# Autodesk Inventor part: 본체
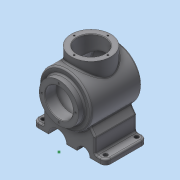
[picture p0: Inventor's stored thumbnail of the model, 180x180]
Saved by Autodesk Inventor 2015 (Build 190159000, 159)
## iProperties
Created: 2018-08
Part Number: 본체
Material: 알루미늄 6061
Document SubType Name: Modeling
Designer: SCD-A18
Density: 2.7 g/cm^3
Appearance: 기본값
Mass: 1879.08 g
Surface Area: 1087.45 cm^2
Volume: 695.956 cm^3
Author: SCD-A18
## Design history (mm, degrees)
sketch "스케치2"
  geometry: L1 (0, 0)-(120, 0); L2 (0, 0)-(0, 27); L3 (0, 38)-(12, 38); L4 (12, 38)-(12, 50); L5 (12, 50)-(120, 50); L6 (120, 50)-(120, 0); L7 (0, 27)-(22, 27); L8 (22, 27)-(22, 40); L9 (22, 40)-(133.746, 40); L10 (0, 0)-(0, 27); L11 (0, 27)-(0, 38); A1 r 116 centre (4, 0) between (120, 0) and (108.671, 50); A2 r 106 centre (4, 0) between (107.419, -23.249) and (102.163, 40)
  constraints: 22 end point, 5 perpendicular, 4 horizontal, 4 point on circle, 3 point on line, 2 centre point, 2 collinear, 2 vertical, 1 coincident
  dimensions: "d0" = 120 distance of L1.end L1.start; "d1" = 76 diameter of L3 L1; "d5" = 12 distance of L3.start L3.end; "d6" = 116 radius of A1; "d9" = 100 diameter of L5 L1; "d10" = 54 diameter of L7 L1; "d12" = 22 distance of L2.end L7.end; "d15" = 106 radius of A2; "d16" = 80 diameter of L9 L1
revolve "회전1" sketch "스케치2" stored, may be unused: angle "d17" = 90 deg
node "작업 평면1"
sketch "스케치3"
  geometry: L1 (0, -38)-(0, 38) reference; L2 (0, 0)-(0, 27); L3 (0, 27)-(22, 27); L4 (22, 27)-(22, 40); L5 (22, 40)-(102.163, 40); L6 (0, 0)-(110, 0); A1 r 116 centre (4, 0) between (108.671, -50) and (108.671, 50) reference; A2 r 106 centre (4, 0) between (110, 0) and (102.163, 40)
  constraints: 10 end point, 3 perpendicular, 2 point on circle, 1 centre point, 1 coincident, 1 horizontal, 1 point on line
  dimensions: "d19" = 10 radial gap between concentric circles of A1 A2; "d20" = 22 distance of L2.end L3.end; "d21" = 54 diameter of L3 L6; "d22" = 80 diameter of L5 L6
revolve "회전2" sketch "스케치3" stored, may be unused: angle "d23" = 90 deg
fillet "모깎기1" dims "d24" = 3
chamfer "모따기1" distance "d25" = 1; stored, may be unused: second distance "d26" = 2, angle "d27" = 45 deg
node "작업 평면2"
node "작업 평면3"
sketch "스케치5"
  geometry: 1 further point
sketch "스케치6"
  geometry: L1 (-20, -70)-(-100, -70); L2 (-100, -70)-(-100, 70); L3 (-100, 70)-(-20, 70); L4 (-20, 70)-(-20, -70); L5 (0, 38)-(0, -38) reference; L6 (-108.671, 50)-(-108.671, -50) reference; L7 (0, 0)-(-120, 0); A1 r 116 centre (-4, 0) between (-108.671, 50) and (-108.671, -50) reference; 3 further points
  constraints: 10 end point, 3 midpoint, 2 parallel, 1 horizontal, 1 horizontal alignment, 1 perpendicular, 1 point on circle, 1 vertical alignment
  dimensions: "d41" = 80 distance of L1.start L1.end; "d42" = 140 distance of L3.end L1.start
extrude "돌출1" join sketch "스케치6" distance "d43" = 10; taper "d44" = 0 deg
sketch "스케치7"
  geometry: L1 (100, 70)-(20, 70) reference; L2 (20, 70)-(20, -70) reference; L3 (20, 50)-(100, 50); L4 (100, 50)-(100, -50); L5 (100, -50)-(20, -50); L6 (20, -50)-(20, 50); 5 further points
  constraints: 8 end point, 4 midpoint, 2 parallel, 1 coincident, 1 collinear, 1 horizontal, 1 perpendicular, 1 vertical alignment
  dimensions: "d45" = 20 distance between parallel lines of L3 L1
extrude "돌출2" join sketch "스케치7" stored distance "d46" = 10; taper "d47" = 0 deg
sketch "스케치8"
  geometry: L1 (140, 0)-(140, 10) reference; L2 (120, 10)-(120, 82) reference; L3 (20, 10)-(20, 82) reference; L4 (0, 0)-(0, 10) reference; L5 (0, 10)-(29.696, 52.41); L6 (140, 10)-(110.304, 52.41); L7 (20, 38.563)-(20, 82); L8 (120, 38.563)-(120, 82); C1 r 50 at (70, 82); A1 r 50 centre (70, 82) between (20, 82) and (120, 82) reference; A2 r 50 centre (70, 82) between (120, 82) and (20, 82) reference
  constraints: 8 end point, 4 point on line, 2 collinear, 2 point on circle, 2 tangent, 1 centre point, 1 coincident, 1 concentric
  dimensions: "d49" = 35 deg angle of L5 L4; "d51" = 35 deg angle of L6 L1
extrude "돌출3" cut sketch "스케치8" stored distance "d52" = 10; taper "d53" = 0 deg
fillet "모깎기2" dims "d54" = 10
fillet "모깎기3" dims "d55" = 3
node "작업 평면4"
sketch "스케치9"
  geometry: L1 (12, -47)-(12, 47) reference; L2 (12, 0)-(120, 0); L3 (0, -38)-(0, 38) reference; C1 r 38 at (62, 0); A1 r 116 centre (4, 0) between (109.49, -48.248) and (109.49, 48.248) reference; 1 further point
  constraints: 2 end point, 1 centre point, 1 midpoint, 1 point on circle, 1 point on line
  dimensions: "d63" = 76 diameter of C1; "d64" = 62 distance from line of L3 C1.centre
extrude "돌출4" join sketch "스케치9" stored distance "d61" = 10; taper "d62" = 0 deg
fillet "모깎기7" dims "d65" = 3
sketch "스케치11"
  geometry: C1 r 38 at (0, 0) reference; C2 r 27 at (0, 0); 1 further point
  constraints: 1 centre point, 1 coincident
  dimensions: "d66" = 54 diameter of C2
extrude "돌출5" cut sketch "스케치11" stored distance "d67" = 10; taper "d68" = 0 deg
sketch "스케치12"
  geometry: C1 r 27 at (0, 0) reference; 5 further points
  constraints: 1 vertical alignment, 5 other
  dimensions: "d69" = 32.5 distance of C1.centre point (0, 32.5); "d72" = 360 deg dimension on C1.centre point (0, 32.5) (derived)
hole "구멍1" sketch "스케치12" at (0, 32.5), (32.5, 0), (0, -32.5), (-32.5, 0) diameter "d74" = 3.242; stored, may be unused: countersink angle "d78" = 90 deg, drill point angle "d80" = 118 deg; dims "d75" = 8, "d76" = 4, "d77" = 2, "d79" = 10
sketch "스케치13"
  geometry: C1 r 38 at (0, 0) reference; 4 further points
  constraints: 1 horizontal alignment, 5 other
  dimensions: "d81" = 32.5 distance of C1.centre point (32.5, 0); "d84" = 360 deg dimension on C1.centre point (32.5, 0) (derived)
hole "구멍2" sketch "스케치13" at (0, 32.5), (-32.5, 0), (0, -32.5), (32.5, 0) diameter "d86" = 3.242; stored, may be unused: countersink angle "d90" = 90 deg, drill point angle "d92" = 118 deg; dims "d87" = 8, "d88" = 4, "d89" = 2, "d91" = 10
chamfer "모따기2" distance "d93" = 1; stored, may be unused: second distance "d94" = 2, angle "d95" = 45 deg
node "작업 평면5"
sketch "스케치15"
  geometry: A1 r 10 centre (90, 60) between (100, 60) and (90, 70) reference; A2 r 10 centre (30, 60) between (30, 70) and (20, 60) reference; A3 r 10 centre (30, -60) between (20, -60) and (30, -70) reference; A4 r 10 centre (90, -60) between (90, -70) and (100, -60) reference; 5 further points
  constraints: 4 coincident
hole "구멍3" sketch "스케치15" at (90, -60), (30, -60), (30, 60), (90, 60) diameter "d98" = 8; stored, may be unused: countersink angle "d102" = 90 deg, drill point angle "d104" = 0 deg; dims "d99" = 8, "d100" = 4, "d101" = 2, "d103" = 10
node "작업 평면6"
sketch "스케치16"
  geometry: C1 r 32.5 at (0, 0); 1 further point
  constraints: 1 centre point, 1 coincident, 1 other
  dimensions: "d106" = 65 diameter of C1
feature "엠보싱1" sketch "스케치16" dims "d0" = 120, "d1" = 76, "d5" = 12, "d6" = 116, "d9" = 100, "d10" = 54, "d12" = 22, "d15" = 106, "d16" = 80, "d107" = 0.5, "d108" = 0
sketch "스케치17"
  geometry: L1 (120, 0)-(0, 0) reference; L2 (60, 0)-(60, 82); C1 r 17.5 at (37.5, 0); C2 r 12.5 at (87.5, 0); A1 r 53 centre (60, 82) between (17.885, 49.824) and (102.115, 49.824) reference; 2 further points
  constraints: 2 centre point, 2 end point, 2 point on line, 1 midpoint, 1 vertical
  dimensions: "d109" = 25 diameter of C2; "d110" = 35 diameter of C1; "d112" = 22.5 distance of L2.start C1.centre; "d113" = 27.5 distance of C2.centre L2.start
extrude "돌출6" cut sketch "스케치17" stored distance "d114" = 10; taper "d115" = 0 deg
fillet "모깎기9" dims "d117" = 3
fillet "모깎기10" dims "d118" = 3
fillet "모깎기11" dims "d119" = 3
fillet "모깎기12" dims "d120" = 3
node "솔리드1"
node "투영된 루프1"
other parameters: "d18" = 0, "d40" = -82, "d59" = -147, "d96" = 130.75, "d105" = 123.5
